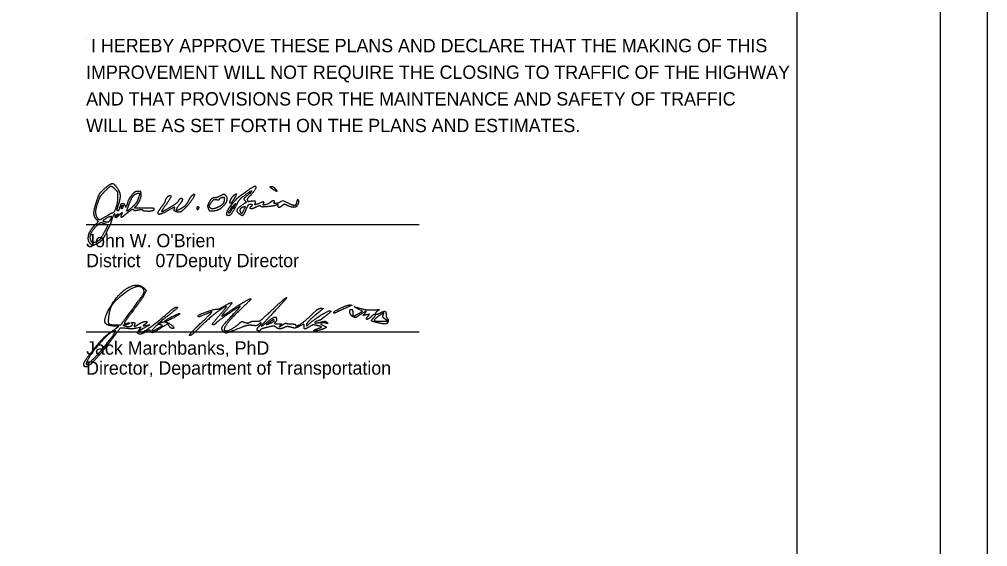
# Model space of a CAD drawing. Extents: x 0 to 34, y 0 to 22.
# Drawn here: x 23.83 to 34, y 5.54 to 11.08 of the extents above; entities that cross this region are included whole.
import ezdxf

# ---------------------------------------------------------------- set-up
doc = ezdxf.new("R2010")
doc.units = 0
for name, color, linetype in [('SH_Border', 7, 'Continuous'), ('SH_Cut_Line', 7, 'Continuous'), ('SH_Data', 7, 'Continuous'), ('SH_Text', 7, 'Continuous')]:
    doc.layers.add(name, color=color, linetype=linetype)

msp = doc.modelspace()

# ---------------------------------------------------------------- linework, layer by layer
at = {"layer": 'SH_Border'}
msp.add_line((32, 0.5), (32, 21.5), dxfattribs=at)
msp.add_lwpolyline([(1.5, 21.5), (33.5, 21.5), (33.5, 0.5), (1.5, 0.5)], close=True, dxfattribs=at)
at = {"layer": 'SH_Cut_Line'}
msp.add_lwpolyline([(0, 0), (34, 0), (34, 22), (0, 22)], close=True, dxfattribs=at)
at = {"layer": 'SH_Data'}
for p, q in [((24.528, 10.875), (24.528, 10.875)), ((24.528, 8.926), (28.028, 8.926)), ((24.528, 7.797), (28.028, 7.797))]:
    msp.add_line(p, q, dxfattribs=at)
at = {"layer": 'SH_Text'}
for p, q in [((26.493, 9.293), (26.493, 9.293)), ((24.99, 8.002), (24.99, 8.002)), ((27.129, 8.001), (27.129, 8.001)), ((25.311, 7.87), (25.311, 7.87)), ((25.356, 7.912), (25.356, 7.912)), ((25.727, 7.883), (25.727, 7.883)), ((26.504, 7.914), (26.504, 7.914)), ((27.582, 7.895), (27.582, 7.895))]:
    msp.add_line(p, q, dxfattribs=at)
for points in [[(26.636, 9.157), (26.597, 9.173), (26.574, 9.165)], [(25.14, 9.097), (25.037, 9.097), (25.056, 9.121)], [(26.068, 9.117), (26.102, 9.15), (26.067, 9.096)], [(24.635, 8.977), (24.654, 8.957), (24.635, 8.935)], [(27.393, 7.991), (27.43, 8.013), (27.389, 8.036)], [(24.843, 7.835), (24.873, 7.856), (24.835, 7.857)], [(25.085, 7.815), (25.107, 7.847), (25.065, 7.837)], [(26.453, 7.894), (26.423, 7.869), (26.464, 7.888)], [(27.642, 7.908), (27.698, 7.908), (27.669, 7.93)]]:
    msp.add_lwpolyline(points, dxfattribs=at)
for points in [[(24.72, 9.3), (24.674, 9.258), (24.656, 9.229), (24.632, 9.156)], [(24.659, 9.177), (24.672, 9.211), (24.69, 9.238), (24.722, 9.271)], [(24.868, 9.29), (24.83, 9.351), (24.781, 9.354), (24.72, 9.3)], [(24.722, 9.271), (24.776, 9.326), (24.8, 9.33), (24.836, 9.292)], [(24.836, 9.292), (24.856, 9.27), (24.859, 9.261), (24.859, 9.218)], [(24.866, 9.126), (24.888, 9.19), (24.888, 9.256), (24.868, 9.29)], [(25.072, 9.272), (25.047, 9.271), (25.036, 9.265), (25.011, 9.236)], [(25.106, 9.248), (25.103, 9.271), (25.101, 9.273), (25.072, 9.272)], [(26.117, 9.147), (26.134, 9.18), (26.173, 9.218), (26.233, 9.26)], [(26.223, 9.279), (26.201, 9.262), (26.172, 9.242), (26.159, 9.233)], [(26.253, 9.23), (26.323, 9.305), (26.302, 9.338), (26.223, 9.279)], [(26.233, 9.26), (26.269, 9.284), (26.266, 9.268), (26.229, 9.236)], [(26.493, 9.293), (26.467, 9.309), (26.459, 9.325), (26.477, 9.324)], [(26.477, 9.324), (26.489, 9.324), (26.506, 9.311), (26.522, 9.291)], [(26.522, 9.291), (26.537, 9.272), (26.525, 9.273), (26.493, 9.293)], [(24.633, 9.027), (24.627, 9.056), (24.638, 9.119), (24.659, 9.177)], [(24.859, 9.218), (24.859, 9.158), (24.822, 9.045), (24.803, 9.045)], [(24.971, 9.179), (24.943, 9.101), (24.945, 9.105), (24.938, 9.124)], [(25.011, 9.236), (24.994, 9.217), (24.976, 9.191), (24.971, 9.179)], [(24.972, 9.119), (24.981, 9.142), (24.992, 9.168), (24.996, 9.178)], [(24.996, 9.178), (25.008, 9.21), (25.052, 9.253), (25.073, 9.253)], [(25.087, 9.235), (25.07, 9.179), (25.045, 9.137), (25.013, 9.108)], [(25.056, 9.121), (25.083, 9.157), (25.108, 9.221), (25.106, 9.248)], [(25.073, 9.253), (25.089, 9.253), (25.091, 9.25), (25.087, 9.235)], [(25.323, 9.113), (25.345, 9.142), (25.363, 9.171), (25.363, 9.177)], [(25.419, 9.221), (25.419, 9.214), (25.379, 9.149), (25.34, 9.095)], [(25.363, 9.177), (25.363, 9.192), (25.395, 9.229), (25.408, 9.229)], [(25.408, 9.229), (25.414, 9.229), (25.419, 9.225), (25.419, 9.221)], [(25.449, 9.13), (25.473, 9.145), (25.496, 9.166), (25.501, 9.177)], [(25.501, 9.177), (25.51, 9.197), (25.539, 9.205), (25.539, 9.186)], [(25.539, 9.186), (25.539, 9.18), (25.525, 9.156), (25.507, 9.133)], [(25.52, 9.091), (25.558, 9.111), (25.588, 9.142), (25.611, 9.186)], [(25.64, 9.229), (25.683, 9.265), (25.629, 9.158), (25.579, 9.108)], [(25.611, 9.186), (25.621, 9.204), (25.634, 9.224), (25.64, 9.229)], [(25.883, 9.205), (25.857, 9.205), (25.831, 9.183), (25.815, 9.149)], [(25.833, 9.098), (25.821, 9.109), (25.828, 9.136), (25.848, 9.163)], [(25.848, 9.163), (25.867, 9.187), (25.873, 9.19), (25.896, 9.186)], [(25.929, 9.221), (25.913, 9.212), (25.892, 9.205), (25.883, 9.205)], [(25.896, 9.186), (25.914, 9.183), (25.925, 9.185), (25.929, 9.192)], [(25.979, 9.19), (25.979, 9.161), (25.95, 9.123), (25.912, 9.106)], [(25.998, 9.225), (25.982, 9.241), (25.965, 9.24), (25.929, 9.221)], [(25.929, 9.192), (25.932, 9.198), (25.945, 9.206), (25.957, 9.209)], [(25.957, 9.209), (25.978, 9.214), (25.979, 9.213), (25.979, 9.19)], [(25.979, 9.128), (26.003, 9.154), (26.014, 9.209), (25.998, 9.225)], [(26.159, 9.233), (26.109, 9.201), (26.003, 9.069), (26.003, 9.039)], [(26.047, 9.149), (26.037, 9.149), (26.036, 9.153), (26.04, 9.167)], [(26.04, 9.167), (26.046, 9.187), (26.069, 9.222), (26.086, 9.236)], [(26.083, 9.197), (26.07, 9.178), (26.059, 9.159), (26.059, 9.155)], [(26.086, 9.236), (26.108, 9.254), (26.106, 9.232), (26.083, 9.197)], [(26.229, 9.236), (26.188, 9.2), (26.183, 9.19), (26.199, 9.173)], [(26.199, 9.173), (26.212, 9.159), (26.211, 9.157), (26.19, 9.144)], [(26.225, 9.179), (26.222, 9.191), (26.23, 9.206), (26.253, 9.23)], [(26.258, 9.168), (26.234, 9.164), (26.229, 9.165), (26.225, 9.179)], [(26.304, 9.145), (26.312, 9.164), (26.293, 9.173), (26.258, 9.168)], [(26.391, 9.14), (26.401, 9.157), (26.387, 9.164), (26.361, 9.153)], [(26.465, 9.158), (26.445, 9.14), (26.381, 9.124), (26.391, 9.14)], [(26.503, 9.157), (26.513, 9.173), (26.482, 9.174), (26.465, 9.158)], [(26.574, 9.165), (26.553, 9.148), (26.494, 9.142), (26.503, 9.157)], [(26.742, 9.168), (26.732, 9.125), (26.701, 9.122), (26.636, 9.157)], [(26.757, 9.182), (26.751, 9.188), (26.746, 9.184), (26.742, 9.168)], [(26.748, 9.125), (26.761, 9.146), (26.766, 9.173), (26.757, 9.182)], [(24.632, 9.156), (24.606, 9.076), (24.607, 9.007), (24.635, 8.977)], [(24.854, 9.071), (24.852, 9.073), (24.857, 9.098), (24.866, 9.126)], [(24.883, 9.111), (24.872, 9.077), (24.862, 9.063), (24.854, 9.071)], [(24.912, 9.141), (24.896, 9.141), (24.891, 9.135), (24.883, 9.111)], [(24.899, 9.1), (24.899, 9.104), (24.9, 9.11), (24.906, 9.125)], [(24.912, 9.104), (24.908, 9.087), (24.899, 9.089), (24.899, 9.1)], [(24.906, 9.125), (24.92, 9.131), (24.913, 9.112), (24.912, 9.104)], [(24.938, 9.124), (24.934, 9.135), (24.925, 9.141), (24.912, 9.141)], [(24.932, 9.024), (24.966, 9.053), (25.026, 9.097), (25.03, 9.072)], [(25.013, 9.108), (24.962, 9.063), (24.951, 9.066), (24.972, 9.119)], [(25.03, 9.072), (25.044, 9.073), (25.068, 9.077), (25.084, 9.08)], [(25.084, 9.08), (25.103, 9.084), (25.115, 9.083), (25.119, 9.077)], [(25.119, 9.077), (25.124, 9.068), (25.209, 9.065), (25.231, 9.073)], [(25.243, 9.087), (25.243, 9.094), (25.212, 9.097), (25.14, 9.097)], [(25.231, 9.073), (25.238, 9.076), (25.243, 9.082), (25.243, 9.087)], [(25.283, 9.048), (25.283, 9.054), (25.301, 9.083), (25.323, 9.113)], [(25.393, 9.073), (25.326, 9.037), (25.283, 9.027), (25.283, 9.048)], [(25.34, 9.095), (25.326, 9.076), (25.317, 9.061), (25.32, 9.061)], [(25.32, 9.061), (25.328, 9.061), (25.408, 9.103), (25.449, 9.13)], [(25.455, 9.089), (25.459, 9.108), (25.458, 9.108), (25.393, 9.073)], [(25.472, 9.06), (25.453, 9.067), (25.45, 9.072), (25.455, 9.089)], [(25.507, 9.133), (25.47, 9.083), (25.475, 9.068), (25.52, 9.091)], [(25.579, 9.108), (25.533, 9.062), (25.502, 9.049), (25.472, 9.06)], [(25.704, 9.109), (25.697, 9.109), (25.691, 9.103), (25.691, 9.096)], [(25.691, 9.096), (25.691, 9.082), (25.708, 9.084), (25.713, 9.099)], [(25.713, 9.099), (25.715, 9.104), (25.711, 9.109), (25.704, 9.109)], [(25.815, 9.149), (25.803, 9.122), (25.803, 9.114), (25.811, 9.093)], [(25.811, 9.093), (25.82, 9.071), (25.825, 9.069), (25.855, 9.069)], [(25.912, 9.106), (25.884, 9.092), (25.842, 9.088), (25.833, 9.098)], [(25.855, 9.069), (25.893, 9.069), (25.948, 9.095), (25.979, 9.128)], [(26.018, 9.021), (26.042, 9.021), (26.068, 9.053), (26.117, 9.147)], [(26.067, 9.096), (26.041, 9.052), (26.027, 9.037), (26.027, 9.054)], [(26.027, 9.054), (26.027, 9.061), (26.033, 9.071), (26.039, 9.077)], [(26.039, 9.077), (26.046, 9.082), (26.051, 9.091), (26.055, 9.097)], [(26.059, 9.155), (26.059, 9.152), (26.054, 9.149), (26.047, 9.149)], [(26.055, 9.097), (26.058, 9.103), (26.059, 9.112), (26.068, 9.117)], [(26.19, 9.144), (26.122, 9.102), (26.104, 9.059), (26.143, 9.034)], [(26.15, 9.057), (26.143, 9.075), (26.159, 9.106), (26.179, 9.111)], [(26.181, 9.073), (26.166, 9.042), (26.157, 9.038), (26.15, 9.057)], [(26.173, 9.021), (26.179, 9.021), (26.194, 9.047), (26.208, 9.079)], [(26.179, 9.111), (26.199, 9.116), (26.199, 9.11), (26.181, 9.073)], [(26.208, 9.079), (26.227, 9.122), (26.237, 9.137), (26.25, 9.139)], [(26.259, 9.113), (26.247, 9.105), (26.25, 9.093), (26.265, 9.093)], [(26.25, 9.139), (26.268, 9.142), (26.275, 9.122), (26.259, 9.113)], [(26.265, 9.093), (26.272, 9.093), (26.294, 9.1), (26.314, 9.11)], [(26.361, 9.153), (26.309, 9.132), (26.299, 9.13), (26.304, 9.145)], [(26.314, 9.11), (26.341, 9.123), (26.353, 9.125), (26.363, 9.118)], [(26.363, 9.118), (26.373, 9.112), (26.401, 9.112), (26.456, 9.117)], [(26.456, 9.117), (26.508, 9.122), (26.547, 9.142), (26.542, 9.117)], [(26.542, 9.117), (26.542, 9.103), (26.568, 9.108), (26.59, 9.125)], [(26.59, 9.125), (26.61, 9.141), (26.612, 9.141), (26.641, 9.127)], [(26.641, 9.127), (26.678, 9.109), (26.737, 9.108), (26.748, 9.125)], [(24.673, 8.973), (24.662, 8.973), (24.637, 9.007), (24.633, 9.027)], [(24.737, 9.009), (24.704, 8.989), (24.675, 8.973), (24.673, 8.973)], [(24.752, 8.95), (24.723, 8.951), (24.706, 8.958), (24.709, 8.966)], [(24.709, 8.966), (24.712, 8.976), (24.786, 9.016), (24.792, 9.011)], [(24.803, 9.045), (24.799, 9.045), (24.769, 9.028), (24.737, 9.009)], [(24.782, 8.978), (24.772, 8.957), (24.763, 8.949), (24.752, 8.95)], [(24.792, 9.011), (24.794, 9.009), (24.79, 8.994), (24.782, 8.978)], [(24.792, 8.944), (24.795, 8.973), (24.836, 9.063), (24.828, 9.002)], [(24.828, 9.002), (24.842, 8.997), (24.857, 9.006), (24.871, 9.02)], [(24.86, 9.02), (24.846, 9.009), (24.833, 9.004), (24.841, 9.016)], [(24.841, 9.016), (24.844, 9.019), (24.848, 9.023), (24.854, 9.029)], [(24.854, 9.029), (24.865, 9.039), (24.868, 9.028), (24.86, 9.02)], [(24.871, 9.02), (24.897, 9.048), (24.912, 9.052), (24.899, 9.029)], [(24.899, 9.029), (24.886, 9.004), (24.905, 9.001), (24.932, 9.024)], [(26.003, 9.039), (26.003, 9.027), (26.008, 9.021), (26.018, 9.021)], [(26.143, 9.034), (26.154, 9.026), (26.167, 9.021), (26.173, 9.021)], [(24.576, 8.865), (24.545, 8.818), (24.549, 8.737), (24.582, 8.715)], [(24.574, 8.816), (24.58, 8.839), (24.631, 8.907), (24.659, 8.93)], [(24.606, 8.905), (24.601, 8.9), (24.588, 8.882), (24.576, 8.865)], [(24.635, 8.935), (24.624, 8.923), (24.611, 8.909), (24.606, 8.905)], [(24.723, 8.852), (24.688, 8.786), (24.659, 8.751), (24.629, 8.74)], [(24.643, 8.724), (24.68, 8.744), (24.718, 8.79), (24.749, 8.855)], [(24.659, 8.93), (24.681, 8.948), (24.683, 8.948), (24.718, 8.936)], [(24.718, 8.936), (24.739, 8.929), (24.755, 8.921), (24.755, 8.919)], [(24.755, 8.919), (24.755, 8.917), (24.741, 8.887), (24.723, 8.852)], [(24.749, 8.855), (24.762, 8.882), (24.776, 8.909), (24.779, 8.916)], [(24.779, 8.916), (24.783, 8.921), (24.786, 8.931), (24.792, 8.944)], [(24.599, 8.733), (24.585, 8.733), (24.568, 8.792), (24.574, 8.816)], [(24.582, 8.715), (24.596, 8.705), (24.61, 8.708), (24.643, 8.724)], [(24.629, 8.74), (24.619, 8.736), (24.605, 8.733), (24.599, 8.733)], [(24.779, 8.053), (24.865, 8.203), (25.073, 8.319), (25.139, 8.253)], [(25.13, 8.244), (25.104, 8.286), (24.978, 8.245), (24.883, 8.163)], [(24.99, 8.002), (25.112, 8.165), (25.144, 8.222), (25.13, 8.244)], [(25.139, 8.253), (25.158, 8.235), (25.158, 8.23), (25.139, 8.191)], [(24.883, 8.163), (24.816, 8.106), (24.777, 8.042), (24.766, 7.971)], [(25.139, 8.191), (25.128, 8.168), (25.077, 8.093), (25.024, 8.023)], [(26.033, 8.011), (26.113, 8.068), (26.244, 8.145), (26.26, 8.145)], [(26.26, 8.145), (26.265, 8.145), (26.224, 8.102), (26.168, 8.05)], [(26.487, 8.031), (26.562, 8.101), (26.628, 8.157), (26.634, 8.157)], [(26.634, 8.157), (26.639, 8.157), (26.587, 8.097), (26.518, 8.024)], [(24.835, 7.857), (24.737, 7.858), (24.714, 7.94), (24.779, 8.053)], [(25.369, 7.979), (25.419, 8.022), (25.465, 8.057), (25.47, 8.057)], [(25.47, 8.057), (25.495, 8.058), (25.472, 8.032), (25.386, 7.965)], [(26.002, 8.064), (25.992, 8.074), (25.782, 7.907), (25.704, 7.828)], [(26.142, 8.064), (26.093, 8.036), (25.905, 7.904), (25.891, 7.888)], [(25.908, 8.035), (25.914, 8.034), (25.943, 8.047), (25.974, 8.065)], [(25.924, 7.964), (25.97, 8.016), (26.005, 8.061), (26.002, 8.064)], [(25.974, 8.065), (26.052, 8.111), (26.065, 8.098), (26.005, 8.03)], [(26.168, 8.05), (26.069, 7.957), (25.979, 7.848), (25.979, 7.821)], [(26.077, 7.985), (26.123, 8.034), (26.152, 8.07), (26.142, 8.064)], [(26.895, 7.975), (26.94, 8.019), (26.977, 8.045), (26.995, 8.044)], [(26.995, 8.044), (27.019, 8.044), (27.016, 8.038), (26.967, 7.998)], [(27.129, 8.001), (27.129, 8.013), (27.282, 8.084), (27.301, 8.08)], [(27.301, 8.08), (27.322, 8.076), (27.323, 8.076), (27.201, 8.022)], [(27.389, 8.036), (27.346, 8.06), (27.345, 8.06), (27.448, 8.034)], [(24.766, 7.971), (24.755, 7.898), (24.776, 7.87), (24.844, 7.87)], [(24.844, 7.87), (24.891, 7.87), (24.895, 7.874), (24.99, 8.002)], [(25.024, 8.023), (24.972, 7.954), (24.929, 7.893), (24.929, 7.888)], [(25.108, 7.795), (25.131, 7.795), (25.257, 7.884), (25.369, 7.979)], [(25.386, 7.965), (25.293, 7.892), (25.271, 7.87), (25.315, 7.894)], [(25.356, 7.912), (25.376, 7.93), (25.508, 7.996), (25.513, 7.99)], [(25.513, 7.99), (25.519, 7.984), (25.377, 7.907), (25.359, 7.907)], [(25.705, 7.967), (25.705, 7.977), (25.892, 8.041), (25.908, 8.035)], [(25.786, 7.982), (25.723, 7.956), (25.704, 7.952), (25.705, 7.967)], [(25.727, 7.883), (25.798, 7.951), (25.854, 8.007), (25.85, 8.007)], [(25.85, 8.007), (25.847, 8.007), (25.818, 7.996), (25.786, 7.982)], [(25.858, 7.87), (25.848, 7.87), (25.877, 7.911), (25.924, 7.964)], [(26.005, 8.03), (25.977, 7.998), (25.954, 7.969), (25.954, 7.964)], [(25.954, 7.964), (25.954, 7.96), (25.99, 7.981), (26.033, 8.011)], [(25.97, 7.799), (25.945, 7.825), (25.973, 7.875), (26.077, 7.985)], [(26.312, 7.909), (26.345, 7.906), (26.369, 7.923), (26.487, 8.031)], [(26.518, 8.024), (26.388, 7.886), (26.356, 7.839), (26.439, 7.907)], [(26.439, 7.907), (26.487, 7.946), (26.529, 7.957), (26.529, 7.929)], [(26.729, 7.868), (26.729, 7.846), (26.825, 7.907), (26.895, 7.975)], [(26.967, 7.998), (26.893, 7.937), (26.842, 7.883), (26.842, 7.866)], [(26.876, 7.884), (26.93, 7.933), (27.077, 8.023), (27.094, 8.017)], [(27.06, 7.976), (27.033, 7.955), (27.008, 7.935), (27.004, 7.931)], [(27.094, 8.017), (27.102, 8.014), (27.087, 7.996), (27.06, 7.976)], [(27.201, 8.022), (27.138, 7.994), (27.129, 7.991), (27.129, 8.001)], [(27.33, 7.957), (27.304, 7.971), (27.293, 8.032), (27.317, 8.032)], [(27.317, 8.032), (27.324, 8.032), (27.329, 8.018), (27.329, 8.001)], [(27.329, 8.001), (27.329, 7.964), (27.344, 7.962), (27.393, 7.991)], [(27.405, 7.975), (27.365, 7.949), (27.352, 7.945), (27.33, 7.957)], [(27.453, 7.987), (27.477, 8.016), (27.461, 8.012), (27.405, 7.975)], [(27.472, 7.975), (27.439, 7.967), (27.437, 7.968), (27.453, 7.987)], [(27.448, 8.034), (27.469, 8.028), (27.514, 8.026), (27.548, 8.028)], [(27.492, 7.964), (27.507, 7.982), (27.505, 7.983), (27.472, 7.975)], [(27.521, 7.955), (27.489, 7.925), (27.466, 7.932), (27.492, 7.964)], [(27.546, 7.943), (27.577, 7.976), (27.555, 7.987), (27.521, 7.955)], [(27.582, 7.895), (27.527, 7.908), (27.522, 7.915), (27.546, 7.943)], [(27.548, 8.028), (27.603, 8.031), (27.608, 8.029), (27.588, 8.014)], [(27.589, 7.953), (27.546, 7.922), (27.563, 7.908), (27.642, 7.908)], [(27.588, 8.014), (27.559, 7.993), (27.582, 7.976), (27.616, 7.994)], [(27.65, 7.976), (27.66, 8.001), (27.651, 7.998), (27.589, 7.953)], [(27.616, 7.994), (27.656, 8.016), (27.679, 8.01), (27.679, 7.979)], [(27.669, 7.93), (27.649, 7.946), (27.643, 7.959), (27.65, 7.976)], [(27.679, 7.979), (27.679, 7.963), (27.686, 7.944), (27.694, 7.936)], [(27.694, 7.936), (27.701, 7.928), (27.704, 7.913), (27.7, 7.902)], [(24.592, 7.593), (24.669, 7.693), (24.749, 7.77), (24.843, 7.835)], [(24.924, 7.835), (24.89, 7.838), (24.879, 7.828), (24.802, 7.726)], [(24.936, 7.869), (24.913, 7.868), (24.914, 7.867), (24.94, 7.857)], [(25.065, 7.837), (25.025, 7.828), (25.002, 7.827), (24.924, 7.835)], [(24.929, 7.888), (24.929, 7.884), (24.945, 7.883), (24.964, 7.888)], [(24.979, 7.883), (24.969, 7.876), (24.949, 7.87), (24.936, 7.869)], [(24.94, 7.857), (24.97, 7.845), (25.026, 7.869), (25.009, 7.887)], [(24.964, 7.888), (24.989, 7.894), (24.993, 7.892), (24.979, 7.883)], [(25.009, 7.887), (25.004, 7.891), (25.01, 7.895), (25.022, 7.895)], [(25.022, 7.895), (25.037, 7.895), (25.042, 7.889), (25.037, 7.876)], [(25.037, 7.876), (25.029, 7.853), (25.041, 7.852), (25.074, 7.874)], [(25.074, 7.874), (25.102, 7.894), (25.167, 7.912), (25.167, 7.9)], [(25.152, 7.846), (25.101, 7.817), (25.081, 7.795), (25.108, 7.795)], [(25.145, 7.876), (25.126, 7.862), (25.128, 7.861), (25.161, 7.865)], [(25.167, 7.9), (25.167, 7.895), (25.157, 7.884), (25.145, 7.876)], [(25.161, 7.865), (25.198, 7.871), (25.198, 7.871), (25.152, 7.846)], [(25.316, 7.838), (25.248, 7.794), (25.21, 7.784), (25.202, 7.809)], [(25.258, 7.854), (25.213, 7.813), (25.225, 7.804), (25.283, 7.834)], [(25.311, 7.87), (25.293, 7.877), (25.277, 7.872), (25.258, 7.854)], [(25.283, 7.834), (25.329, 7.858), (25.333, 7.862), (25.311, 7.87)], [(25.315, 7.894), (25.328, 7.901), (25.351, 7.903), (25.368, 7.899)], [(25.401, 7.857), (25.384, 7.881), (25.382, 7.881), (25.316, 7.838)], [(25.359, 7.907), (25.354, 7.907), (25.353, 7.909), (25.356, 7.912)], [(25.368, 7.899), (25.404, 7.889), (25.463, 7.832), (25.436, 7.832)], [(25.436, 7.832), (25.426, 7.832), (25.411, 7.844), (25.401, 7.857)], [(25.617, 7.758), (25.607, 7.758), (25.656, 7.815), (25.727, 7.883)], [(25.891, 7.888), (25.883, 7.878), (25.868, 7.87), (25.858, 7.87)], [(26.169, 7.847), (26.023, 7.789), (25.988, 7.781), (25.97, 7.799)], [(25.998, 7.807), (26.019, 7.807), (26.101, 7.853), (26.137, 7.885)], [(26.137, 7.885), (26.157, 7.903), (26.17, 7.906), (26.194, 7.897)], [(26.275, 7.864), (26.246, 7.868), (26.206, 7.861), (26.169, 7.847)], [(26.194, 7.897), (26.214, 7.889), (26.233, 7.89), (26.249, 7.899)], [(26.249, 7.899), (26.262, 7.906), (26.291, 7.911), (26.312, 7.909)], [(26.344, 7.878), (26.329, 7.864), (26.307, 7.86), (26.275, 7.864)], [(26.341, 7.807), (26.323, 7.807), (26.327, 7.84), (26.348, 7.857)], [(26.367, 7.886), (26.367, 7.893), (26.357, 7.89), (26.344, 7.878)], [(26.348, 7.857), (26.359, 7.866), (26.367, 7.879), (26.367, 7.886)], [(26.436, 7.845), (26.397, 7.836), (26.363, 7.824), (26.359, 7.818)], [(26.52, 7.847), (26.509, 7.858), (26.489, 7.858), (26.436, 7.845)], [(26.504, 7.914), (26.504, 7.927), (26.48, 7.918), (26.453, 7.894)], [(26.464, 7.888), (26.486, 7.899), (26.504, 7.911), (26.504, 7.914)], [(26.514, 7.897), (26.503, 7.886), (26.509, 7.882), (26.541, 7.882)], [(26.529, 7.929), (26.529, 7.92), (26.523, 7.906), (26.514, 7.897)], [(26.616, 7.845), (26.585, 7.828), (26.538, 7.829), (26.52, 7.847)], [(26.541, 7.882), (26.579, 7.882), (26.581, 7.88), (26.565, 7.861)], [(26.565, 7.861), (26.553, 7.846), (26.56, 7.848), (26.587, 7.867)], [(26.587, 7.867), (26.609, 7.882), (26.629, 7.891), (26.633, 7.887)], [(26.681, 7.845), (26.654, 7.852), (26.631, 7.852), (26.616, 7.845)], [(26.633, 7.887), (26.637, 7.883), (26.66, 7.88), (26.685, 7.88)], [(26.77, 7.856), (26.732, 7.837), (26.714, 7.835), (26.681, 7.845)], [(26.685, 7.88), (26.709, 7.88), (26.729, 7.875), (26.729, 7.868)], [(26.817, 7.856), (26.817, 7.879), (26.816, 7.879), (26.77, 7.856)], [(26.879, 7.853), (26.834, 7.826), (26.817, 7.827), (26.817, 7.856)], [(26.842, 7.866), (26.842, 7.859), (26.857, 7.867), (26.876, 7.884)], [(26.962, 7.861), (26.923, 7.871), (26.906, 7.869), (26.879, 7.853)], [(26.97, 7.915), (26.921, 7.899), (26.94, 7.885), (26.992, 7.899)], [(26.948, 7.826), (26.962, 7.831), (26.982, 7.838), (26.992, 7.842)], [(26.992, 7.842), (27.003, 7.846), (26.992, 7.853), (26.962, 7.861)], [(27.004, 7.931), (27.001, 7.927), (26.986, 7.919), (26.97, 7.915)], [(26.992, 7.899), (27.03, 7.909), (27.045, 7.909), (27.058, 7.897)], [(27.039, 7.889), (27.002, 7.898), (26.989, 7.875), (27.023, 7.862)], [(27.023, 7.862), (27.054, 7.85), (27.045, 7.835), (26.998, 7.82)], [(27.058, 7.897), (27.07, 7.884), (27.067, 7.882), (27.039, 7.889)], [(27.7, 7.902), (27.692, 7.881), (27.651, 7.878), (27.582, 7.895)], [(24.835, 7.806), (24.814, 7.827), (24.596, 7.601), (24.55, 7.511)], [(24.62, 7.529), (24.687, 7.598), (24.843, 7.798), (24.835, 7.806)], [(25.084, 7.775), (25.066, 7.782), (25.066, 7.786), (25.085, 7.815)], [(25.151, 7.795), (25.125, 7.78), (25.095, 7.771), (25.084, 7.775)], [(25.202, 7.809), (25.199, 7.817), (25.18, 7.812), (25.151, 7.795)], [(25.704, 7.828), (25.667, 7.789), (25.627, 7.758), (25.617, 7.758)], [(25.979, 7.821), (25.979, 7.814), (25.988, 7.807), (25.998, 7.807)], [(26.359, 7.818), (26.356, 7.812), (26.348, 7.807), (26.341, 7.807)], [(26.998, 7.82), (26.952, 7.805), (26.904, 7.81), (26.948, 7.826)], [(24.802, 7.726), (24.65, 7.524), (24.504, 7.395), (24.504, 7.462)], [(24.504, 7.462), (24.504, 7.472), (24.544, 7.531), (24.592, 7.593)], [(24.55, 7.511), (24.518, 7.45), (24.55, 7.458), (24.62, 7.529)]]:
    msp.add_open_spline(points, degree=2, dxfattribs=at)

# ---------------------------------------------------------------- texts
at = {"layer": 'SH_Data'}
for s, p in [(' I HEREBY APPROVE THESE PLANS AND DECLARE THAT THE MAKING OF THIS', (24.528, 10.735)), ('IMPROVEMENT WILL NOT REQUIRE THE CLOSING TO TRAFFIC OF THE HIGHWAY', (24.528, 10.455)), ('AND THAT PROVISIONS FOR THE MAINTENANCE AND SAFETY OF TRAFFIC', (24.528, 10.175)), ('WILL BE AS SET FORTH ON THE PLANS AND ESTIMATES.', (24.528, 9.895))]:
    msp.add_text(s, height=0.14, dxfattribs=at).set_placement(p)
at = {"layer": 'SH_Text'}
for s, p in [("John W. O'Brien", (24.528, 8.686)), ('District       Deputy Director', (24.528, 8.476)), ('              07', (24.528, 8.476)), ('Jack Marchbanks, PhD', (24.528, 7.557)), ('Director, Department of Transportation', (24.528, 7.347))]:
    msp.add_text(s, height=0.14, dxfattribs=at).set_placement(p)

doc.saveas('drawing.dxf')
